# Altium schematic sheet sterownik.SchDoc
size A4
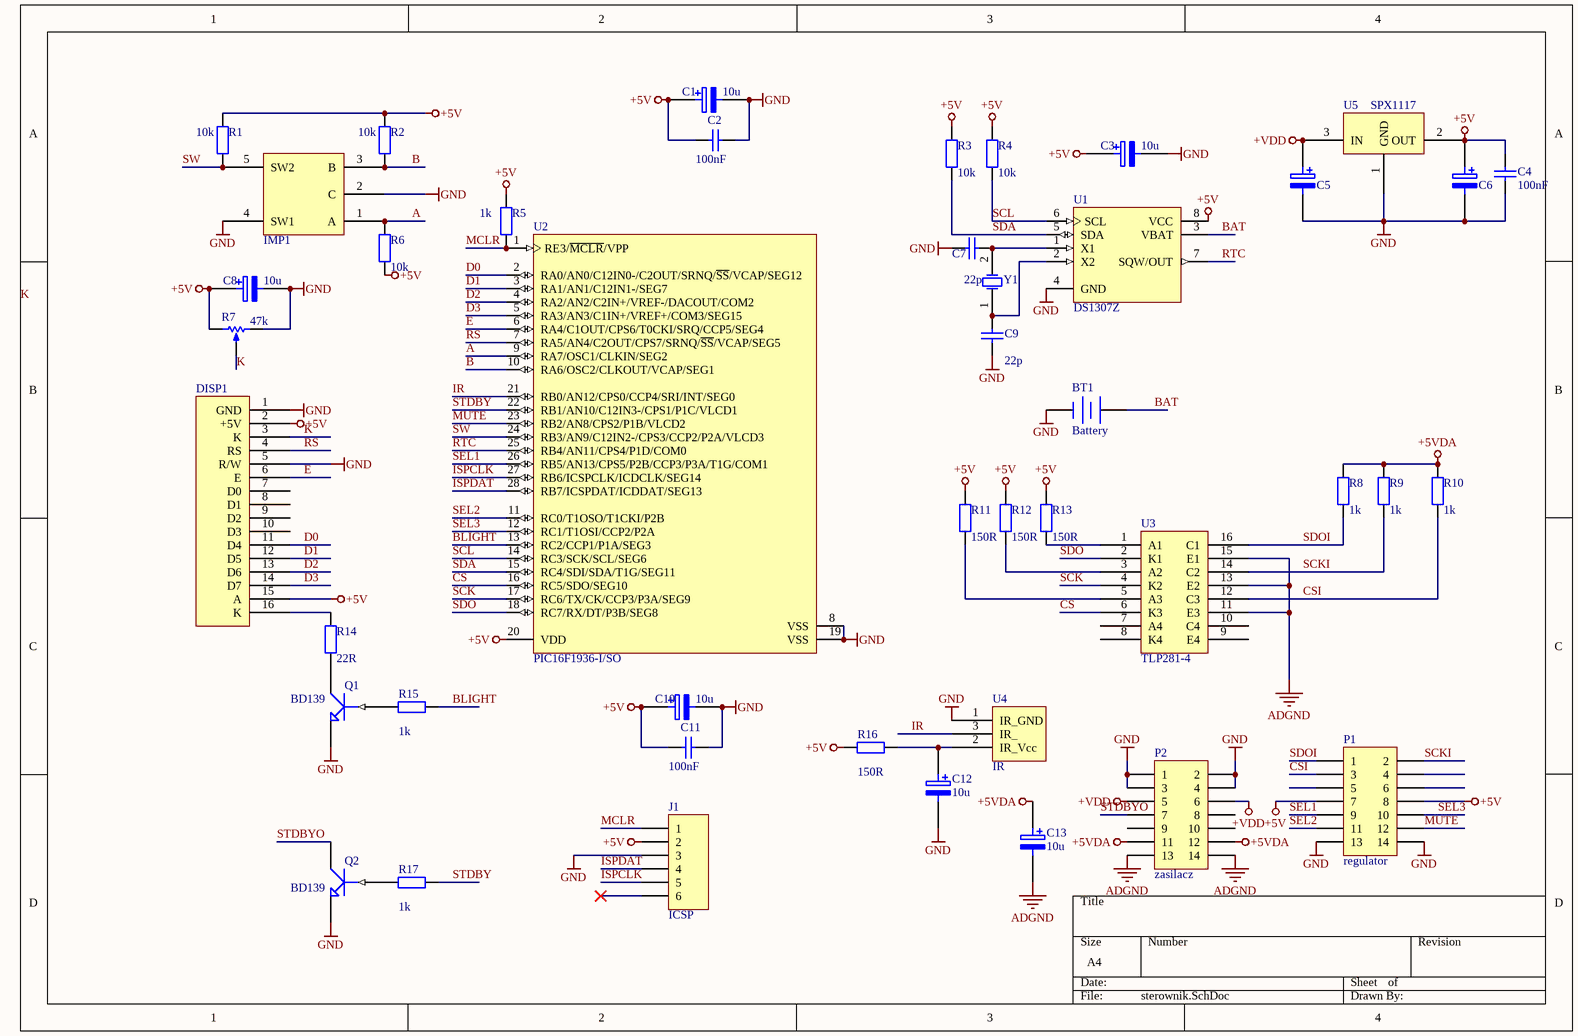
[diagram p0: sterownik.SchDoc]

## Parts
BT1  Battery  [BAT]
C1  value 10u  [3528]
C2  value 100nF  [C1206]  (hidden comment: Cap)
C3  value 10u  [3528]
C4  value 100nF  [C1206]  (hidden comment: Cap)
C5  ELECTRO2  [3528]  (value not drawn)
C6  ELECTRO2  [3528]  (value not drawn)
C7  value 22p  [C1206]  (hidden comment: Cap)
C8  value 10u  [3528]
C9  value 22p  [C1206]  (hidden comment: Cap)
C10  value 10u  [3528]
C11  value 100nF  [C1206]  (hidden comment: Cap)
C12  value 10u  [3528]
C13  value 10u  [3528]
DISP1  LCD  [LCD4x20]  (value not drawn)
IMP1  IMP_PIHER  [IMP_PIHER]  (value not drawn)
J1  ICSP  [HDR1X6]
P1  regulator  [HDR2X7]
P2  zasilacz  [HDR2X7]
Q1  value BD139  [BD139]
Q2  BD139  [BD139]
R1  value 10k  [1206]
R2  value 10k  [1206]
R3  value 10k  [1206]
R4  value 10k  [1206]
R5  value 1k  [1206]
R6  value 10k  [1206]
R7  value 47k  [PR]  (hidden comment: RPot)
R8  value 1k  [1206]
R9  value 1k  [1206]
R10  value 1k  [1206]
R11  value 150R  [1206]
R12  value 150R  [1206]
R13  value 150R  [1206]
R14  value 22R  [1206]
R15  value 1k  [1206]
R16  value 150R  [1206]
R17  value 1k  [1206]
U1  DS1307Z  [SOIC8N_N]
U2  PIC16F1936-I/SO  [SOIC-SO28_N]
U3  TLP281-4  [TLP281-4]
U4  IR  [IR]
U5  SPX1117  [SOT223_N]
Y1  XTAL  [RAD0.1]  (value not drawn)

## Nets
+5V: C1.1 C2.1 C3.1 C4.2 C6.1 C8.1 C10.1 C11.1 DISP1.2(+5V) DISP1.15(A) J1.2 P1.7 P1.8 R1.1 R2.1 R3.1 R4.1 R5.2 R6.1 R7.1(TOP) R11.1 R12.1 R13.1 R16.1 U1.8(VCC) U2.20(VDD) U5.2(OUT)
+5VDA: C13.1 P2.11 P2.12 R8.1 R9.1 R10.1
+VDD: C5.1 P2.5 P2.6 U5.3(IN)
ADGND: C13.2 P2.13 P2.14 U3.11(E3) U3.13(E2) U3.15(E1)
GND: BT1.2(-) C1.2 C2.2 C3.2 C4.1 C5.2 C6.2 C7.2 C8.2 C9.2 C10.2 C11.2 C12.2 DISP1.1(GND) DISP1.5(R/W) IMP1.2(C) IMP1.4(SW1) J1.3 P1.13 P1.14 P2.1 P2.2 P2.3 P2.4 Q1.3(E) Q2.3(E) R7.2(BOT) U1.4(GND) U2.8(VSS) U2.19(VSS) U4.1(IR_GND) U5.1(GND)
A: IMP1.1(A) R6.2 U2.9(RA7/OSC1/CLKIN/SEG2)
B: IMP1.3(B) R2.2 U2.10(RA6/OSC2/CLKOUT/VCAP/SEG1)
BAT: BT1.1(+) U1.3(VBAT)
BLIGHT: R15.1 U2.13(RC2/CCP1/P1A/SEG3)
CS: U2.16(RC5/SDO/SEG10) U3.6(K3)
CSI: P1.3 R10.2 U3.12(C3)
D0: DISP1.11(D4) U2.2(RA0/AN0/C12IN0-/C2OUT/SRNQ/~{SS}/VCAP/SEG12)
D1: DISP1.12(D5) U2.3(RA1/AN1/C12IN1-/SEG7)
D2: DISP1.13(D6) U2.4(RA2/AN2/C2IN+/VREF-/DACOUT/COM2)
D3: DISP1.14(D7) U2.5(RA3/AN3/C1IN+/VREF+/COM3/SEG15)
E: DISP1.6(E) U2.6(RA4/C1OUT/CPS6/T0CKI/SRQ/CCP5/SEG4)
IR: U2.21(RB0/AN12/CPS0/CCP4/SRI/INT/SEG0) U4.3(IR_)
ISPCLK: J1.5 U2.27(RB6/ICSPCLK/ICDCLK/SEG14)
ISPDAT: J1.4 U2.28(RB7/ICSPDAT/ICDDAT/SEG13)
K: DISP1.3(K) R7.3(TAP)
MCLR: J1.1 R5.1 U2.1(RE3/~{MCLR}/VPP)
MUTE: P1.12 U2.23(RB2/AN8/CPS2/P1B/VLCD2)
RS: DISP1.4(RS) U2.7(RA5/AN4/C2OUT/CPS7/SRNQ/~{SS}/VCAP/SEG5)
RTC: U1.7(SQW/OUT) U2.25(RB4/AN11/CPS4/P1D/COM0)
SCK: U2.17(RC6/TX/CK/CCP3/P3A/SEG9) U3.4(K2)
SCKI: P1.2 R9.2 U3.14(C2)
SCL: R4.2 U1.6(SCL) U2.14(RC3/SCK/SCL/SEG6)
SDA: R3.2 U1.5(SDA) U2.15(RC4/SDI/SDA/T1G/SEG11)
SDO: U2.18(RC7/RX/DT/P3B/SEG8) U3.2(K1)
SDOI: P1.1 R8.2 U3.16(C1)
SEL1: P1.9 U2.26(RB5/AN13/CPS5/P2B/CCP3/P3A/T1G/COM1)
SEL2: P1.11 U2.11(RC0/T1OSO/T1CKI/P2B)
SEL3: P1.10 U2.12(RC1/T1OSI/CCP2/P2A)
STDBY: R17.1 U2.22(RB1/AN10/C12IN3-/CPS1/P1C/VLCD1)
STDBYO: P2.7 Q2.2(C)
SW: IMP1.5(SW2) R1.2 U2.24(RB3/AN9/C12IN2-/CPS3/CCP2/P2A/VLCD3)
NetC7_1: C7.1 U1.1(X1) Y1.2(OSC2)
NetC9_1: C9.1 U1.2(X2) Y1.1(OSC1)
NetC12_1: C12.1 R16.2 U4.2(IR_Vcc)
NetDISP1_16: DISP1.16(K) R14.1
NetQ1_1: Q1.1(B) R15.2
NetQ1_2: Q1.2(C) R14.2
NetQ2_1: Q2.1(B) R17.2
NetR11_2: R11.2 U3.5(A3)
NetR12_2: R12.2 U3.3(A2)
NetR13_2: R13.2 U3.1(A1)

Not connected (* = marked no-connect by the designer): DISP1 7(D0) 8(D1) 9(D2) 10(D3); J1 6*; P1 4 5 6; P2 8 9 10; U3 7(A4) 8(K4) 9(E4) 10(C4)

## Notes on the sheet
- Labels drawn without touching a wire or pin: K

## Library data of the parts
BT1 = Battery: Multicell Battery
C1 C3 C5 C6 C8 C10 C12 C13 = ELECTRO2: Electrolytic Capacitor
C2 C4 C7 C9 C11 = Cap: Capacitor
J1 = Header 6: Header, 6-Pin
P1 P2 = Header 7X2: Header, 7-Pin, Dual row
Q1 Q2 = NPN1: NPN Transistor
R1-R6 R8-R17 = Res2: Resistor
R7 = RPot: Potentiometer; Sim Note: Enter the Resistance value and the set point into parameter fields.; Set Position: 0.5
U1 = DS1307Z: 64 X 8 Serial Real-Time Clock
U2 = PIC16F1936-I/SO: CMOS Microcontroller with LCD Driver, 8K (words) Program Memory, 256 Bytes Data Memory, 512 Bytes SRAM, 25 I/O's, 1.8V-5.5V, 28-Pin SOIC, Industrial Temperature; Manufacturer: Microchip
Y1 = XTAL: Crystal Oscillator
